Omron CX-Programmer project 新工程 (CX-Programmer 9.50)

# PLC 新PLC1: CP1E NA

## Global symbols (name address type ; comment)
W30.00 BOOL  ; 吊钩上升脉冲开始
W0.00 BOOL  ; 小车正向脉冲开始
2.00 BOOL  ; 大车正向脉冲开始
C000 BOOL  ; 小车距离脉冲
C001 BOOL  ; 大车距离
C002 BOOL  ; 吊钩距离
D0 CHANNEL  ; 小车当前值
D1 CHANNEL  ; 大车当前值
D2 CHANNEL  ; 吊钩当前值
W0.01 BOOL  ; 小车反向脉冲开始
W2.01 BOOL  ; 大车反向脉冲开始
W3.01 BOOL  ; 吊钩下降脉冲开始
W4.00 BOOL  ; 启动滚筒
W4.01 BOOL  ; 停止滚筒
W4.02 BOOL  ; 滚筒动作

## Program 新程序1 (cyclic task 0)

### Section 段1

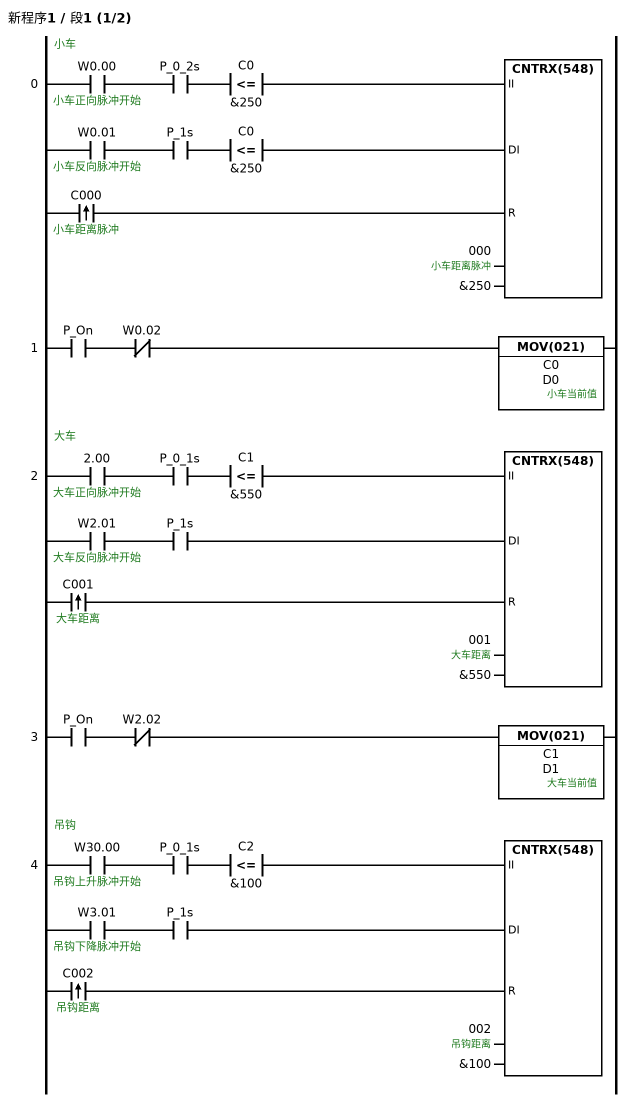
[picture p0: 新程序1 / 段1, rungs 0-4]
; rung 0: 小车
LD W0.00  ; 小车正向脉冲开始
AND P_0_2s
AND<=(315) C0 &250
LD W0.01  ; 小车反向脉冲开始
AND P_1s
AND<=(315) C0 &250
@LD C000  ; 小车距离脉冲
CNTRX(548) 000 &250  ; 小车距离脉冲
; rung 1
LD P_On
ANDNOT W0.02
MOV(021) C0 D0  ; 小车当前值
; rung 2: 大车
LD 2.00  ; 大车正向脉冲开始
AND P_0_1s
AND<=(315) C1 &550
LD W2.01  ; 大车反向脉冲开始
AND P_1s
@LD C001  ; 大车距离
CNTRX(548) 001 &550  ; 大车距离
; rung 3
LD P_On
ANDNOT W2.02
MOV(021) C1 D1  ; 大车当前值
; rung 4: 吊钩
LD W30.00  ; 吊钩上升脉冲开始
AND P_0_1s
AND<=(315) C2 &100
LD W3.01  ; 吊钩下降脉冲开始
AND P_1s
@LD C002  ; 吊钩距离
CNTRX(548) 002 &100  ; 吊钩距离

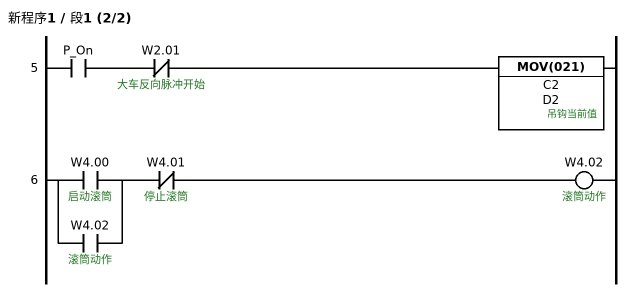
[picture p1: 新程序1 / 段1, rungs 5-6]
; rung 5
LD P_On
ANDNOT W2.01  ; 大车反向脉冲开始
MOV(021) C2 D2  ; 吊钩当前值
; rung 6
LD W4.00  ; 启动滚筒
OR W4.02  ; 滚筒动作
ANDNOT W4.01  ; 停止滚筒
OUT W4.02  ; 滚筒动作

### Section END
; rung 0
END(001)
